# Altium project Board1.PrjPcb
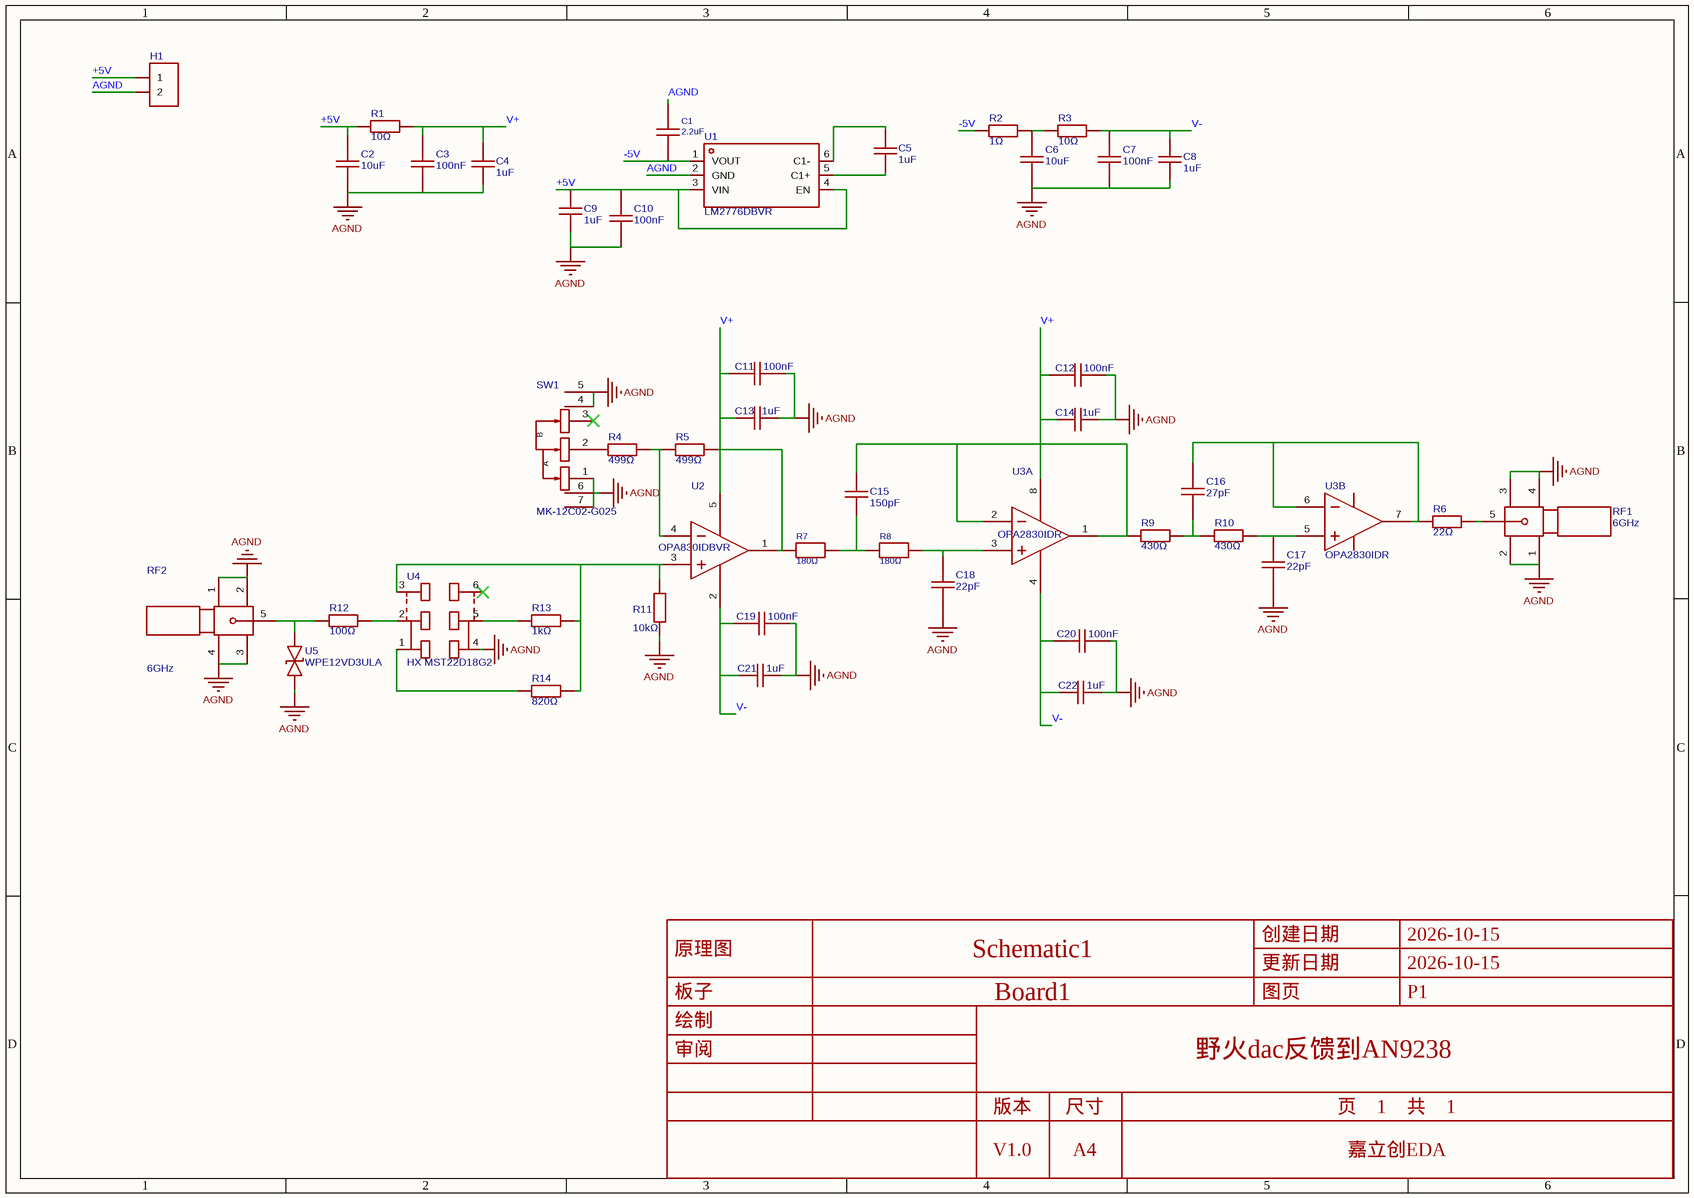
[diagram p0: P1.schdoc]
1 sheet, 45 parts. Net scope: global (net labels, ports and power ports of the same name join across sheets).
Board file: PCB1.pcbdoc

## Sheet P1.schdoc
size 297 x 209 mm; Symbol: Drawing-Symbol_A4; Device: Drawing-Symbol_A4; Company: 嘉立创EDA; Version: V1.0; Page Size: A4; @Project Name: 野火dac反馈到AN9238; @Update Date: 2026-10-15; @Create Date: 2026-10-15; @Board Name: Board1; @Page Name: P1; @Create Time: 21:12:31; @Page Count: 1; @Page No: 1; @Schematic Name: Schematic1; @Update Time: 21:12:31; @Assembly Variant: Basic; Border: 1; Title Block Position: 3; Size: A4; Width: 1170; Height: 825; Region Start: 1; X Region Count: 6; Y Region Count: 4; Blade Width: 10

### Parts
C1  2.2uF  [C0805]
C2  10uF  [C0805]
C3  100nF  [C0603]
C4  1uF  [C0603]
C5  1uF  [C0603]
C6  10uF  [C0805]
C7  100nF  [C0603]
C8  1uF  [C0603]
C9  1uF  [C0603]
C10  100nF  [C0603]
C11  100nF  [C0603]
C12  100nF  [C0603]
C13  1uF  [C0603]
C14  1uF  [C0603]
C15  150pF  [C0603]
C16  27pF  [C0603]
C17  22pF  [C0603]
C18  22pF  [C0603]
C19  100nF  [C0603]
C20  100nF  [C0603]
C21  1uF  [C0603]
C22  1uF  [C0603]
H1  (no value)  [HDR-TH_2P-P2.54-V-F]
R1  10Ω  [R0603]
R2  1Ω  [R0603]
R3  10Ω  [R0603]
R4  499Ω  [R0603]
R5  499Ω  [R0603]
R6  22Ω  [R0603]
R7  180Ω  [R0603]
R8  180Ω  [R0603]
R9  430Ω  [R0603]
R10  430Ω  [R0603]
R11  10kΩ  [R0603]
R12  100Ω  [R0603]
R13  1kΩ  [R0603]
R14  820Ω  [R0603]
RF1  6GHz  [SMA-TH_SMA-KWE902]
RF2  6GHz  [SMA-TH_SMA-KWE902]
SW1  MK-12C02-G025  [SW-SMD_MK-12C02-G025]
U1  LM2776DBVR  [SOT-23-6_L2.9-W1.6-P0.95-LS2.8-BR]
U2  OPA830IDBVR  [SOT-23-5_L2.9-W1.6-P0.95-LS2.8-BR]
U3  OPA2830IDR  [SOIC-8_L5.0-W4.0-P1.27-LS6.0-BL]  (parts A,B of 2)
U4  HX MST22D18G2  [SW-SMD_MST22D18G2]
U5  WPE12VD3ULA  [SOD-323_L1.7-W1.3-LS2.5-BI]

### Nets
AGND: C1.2 C2.1 C3.1 C4.1 C6.1 C7.1 C8.1 C9.1 C10.1 C11.1 C12.1 C13.1 C14.1 C17.1 C18.1 C19.2 C20.2 C21.2 C22.2 H1.2 R11.1 RF1.1 RF1.2 RF1.3 RF1.4 RF2.1 RF2.2 RF2.3 RF2.4 SW1.1 SW1.4 SW1.5 SW1.6 SW1.7 U1.2(GND) U4.4 U5.1
+5V: C2.2 C9.2 C10.2 H1.1 R1.1 U1.3(VIN) U1.4(EN)
-5V: C1.1 R2.1 U1.1(VOUT)
V+: C3.2 C4.2 C11.2 C12.2 C13.2 C14.2 R1.2 U2.5(+VS) U3.8(VS+)
V-: C7.2 C8.2 C19.1 C20.1 C21.1 C22.1 R3.2 U2.2(−VS) U3.4(VS-)
NetC5_1: C5.1 U1.5(C1+)
NetC5_2: C5.2 U1.6(C1-)
NetC6_2: C6.2 R2.2 R3.1
NetC15_1: C15.1 R9.1 U3.1(OUT1) U3.2(IN1-)
NetC15_2: C15.2 R7.2 R8.1
NetC16_1: C16.1 R9.2 R10.1
NetC16_2: C16.2 R6.1 U3.6(IN2-) U3.7(OUT2)
NetC17_2: C17.2 R10.2 U3.5(IN2+)
NetC18_2: C18.2 R8.2 U3.3(IN1+)
NetR4_1: R4.1 SW1.2
NetR4_2: R4.2 R5.1 U2.4(IN-)
NetR5_2: R5.2 R7.1 U2.1(Output)
NetR6_2: R6.2 RF1.5
NetR11_2: R11.2 R13.2 R14.2 U2.3(IN+) U4.3
NetR12_1: R12.1 RF2.5 U5.2
NetR12_2: R12.2 U4.2
NetR13_1: R13.1 U4.5
NetR14_1: R14.1 U4.1

Not connected (* = marked no-connect by the designer): SW1 3*; U4 6*

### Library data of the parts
C1 = CGA0805X7R225M250MT: 容值:2.2uF;精度:±20%;额定电压:25V;温度系数:X7R;; Manufacturer: HRE(芯声); AddInBom: yes; ModelId: 1ba041120af144c991958decab20d2410819f05c4eef4c71ace90d822a990e87; ModelName: C0805_L2.0-W1.3-H1.3; ModelTransform: 78.74,51.181,0,0,0,0,0,0.0005,0; Tolerance: ±20%; Voltage Rating: 25V; Temperature Coefficient: X7R
C2 C6 = 0805X106K250NT: 容值:10uF;精度:±10%;额定电压:25V;温度系数:X5R;; Manufacturer: FH(风华); Symbol: CL21A106KAYNNNE; AddInBom: yes; ModelId: 1ba041120af144c991958decab20d2410819f05c4eef4c71ace90d822a990e87; ModelName: C0805_L2.0-W1.3-H1.3; ModelTransform: 78.74,51.181,0,0,0,0,0,0.0005,0; Tolerance: ±10%; Voltage Rating: 25V; Temperature Coefficient: X5R
C3 C7 C12 C20 = CL10B104KB8NNNC: 容值:100nF;精度:±10%;额定电压:50V;温度系数:X7R;; Manufacturer: SAMSUNG(三星); AddInBom: yes; ModelId: ac125912035d415993ca9572d50418b10819f05c4eef4c71ace90d822a990e87; ModelName: C0603_L1.6-W0.8-H0.8; ModelTransform: 62.992,31.496,0,0,0,0,0,0,0; Tolerance: ±10%; Voltage Rating: 50V; Temperature Coefficient: X7R
C4 C8 C14 C22 = CL10A105KA8NNNC: 容值:1uF;精度:±10%;额定电压:25V;温度系数:X5R;; Manufacturer: SAMSUNG(三星); AddInBom: yes; ModelId: ac125912035d415993ca9572d50418b10819f05c4eef4c71ace90d822a990e87; ModelName: C0603_L1.6-W0.8-H0.8; ModelTransform: 62.992,31.496,0,0,0,0,0,0,0; Tolerance: ±10%; Voltage Rating: 25V; Temperature Coefficient: X5R
C5 C9 C13 C21 = CL10A105KA8NNNC: 容值:1uF;精度:±10%;额定电压:25V;温度系数:X5R;; Manufacturer: SAMSUNG(三星); 3D Model: ac125912035d415993ca9572d50418b10819f05c4eef4c71ace90d822a990e87; 3D Model Transform: 62.992,31.496,0,0,0,0,0,0,0; Tolerance: ±10%; Voltage Rating: 25V; Temperature Coefficient: X5R; AddInBom: yes; ModelName: C0603_L1.6-W0.8-H0.8
C10 C11 C19 = CL10B104KB8NNNC: 容值:100nF;精度:±10%;额定电压:50V;温度系数:X7R;; Manufacturer: SAMSUNG(三星); 3D Model: ac125912035d415993ca9572d50418b10819f05c4eef4c71ace90d822a990e87; 3D Model Transform: 62.992,31.496,0,0,0,0,0,0,0; Tolerance: ±10%; Voltage Rating: 50V; Temperature Coefficient: X7R; AddInBom: yes; ModelName: C0603_L1.6-W0.8-H0.8
C15 = 0603CG151J500NT: 容值:150pF;精度:±5%;额定电压:50V;温度系数:C0G;; Manufacturer: FH(风华); AddInBom: yes; ModelId: ac125912035d415993ca9572d50418b10819f05c4eef4c71ace90d822a990e87; ModelName: C0603_L1.6-W0.8-H0.8; ModelTransform: 62.992,31.496,0,0,0,0,0,0,0; Tolerance: ±5%; Voltage Rating: 50V; Temperature Coefficient: C0G
C16 = 0603CG270J500NT: 容值:27pF;精度:±5%;额定电压:50V;温度系数:C0G;; Manufacturer: FH(风华); AddInBom: yes; ModelId: ac125912035d415993ca9572d50418b10819f05c4eef4c71ace90d822a990e87; ModelName: C0603_L1.6-W0.8-H0.8; ModelTransform: 62.992,31.496,0,0,0,0,0,0,0; Tolerance: ±5%; Voltage Rating: 50V; Temperature Coefficient: C0G
C17 C18 = 0603CG220J500NT: 容值:22pF;精度:±5%;额定电压:50V;温度系数:C0G;; Manufacturer: FH(风华); AddInBom: yes; ModelId: ac125912035d415993ca9572d50418b10819f05c4eef4c71ace90d822a990e87; ModelName: C0603_L1.6-W0.8-H0.8; ModelTransform: 62.992,31.496,0,0,0,0,0,0,0; Tolerance: ±5%; Voltage Rating: 50V; Temperature Coefficient: C0G
H1 = HDR-F_2.54_1x2P: Symbol: Header-Female-2.54_1x2; ConvertToPcb: yes; ModelId: a9450ef445564560a104363b9aacde4e0819f05c4eef4c71ace90d822a990e87; ModelName: HDR-TH_2P-P2.54-F-LI-1X2P; ModelTransform: 215.7476,98.425,0,0,0,0,0,0,-129.921
R1 R3 = 0603WAF100JT5E: 电阻类型:厚膜电阻;阻值:10Ω;精度:±1%;功率:100mW;工作电压:75V;温度系数:±400ppm/℃;; Manufacturer: UNI-ROYAL(厚声); AddInBom: yes; ModelId: fc143cca1e79419f9cd78b61e9279f080819f05c4eef4c71ace90d822a990e87; ModelTransform: 31.8897,63.7794,0,90,0,0,0,0,0; Tolerance: ±1%; Power(Watts): 100mW; Voltage-Supply(Max): 75V
R2 = AC0603FR-071RL: 电阻类型:厚膜电阻;阻值:1Ω;精度:±1%;功率:100mW;工作电压:75V;温度系数:±200ppm/℃;; Manufacturer: YAGEO(国巨); Symbol: 0603WAF100KT5E; AddInBom: yes; ModelId: fc143cca1e79419f9cd78b61e9279f080819f05c4eef4c71ace90d822a990e87; ModelTransform: 31.8897,63.7794,0,90,0,0,0,0,0; Tolerance: ±1%; Power(Watts): 100mW; Voltage-Supply(Max): 75V
R4 R5 = RC0603FR-07499RL: 电阻类型:厚膜电阻;阻值:499Ω;精度:±1%;功率:100mW;工作电压:75V;温度系数:±100ppm/℃;; Manufacturer: YAGEO(国巨); AddInBom: yes; ModelId: fc143cca1e79419f9cd78b61e9279f080819f05c4eef4c71ace90d822a990e87; ModelTransform: 31.8897,63.7794,0,90,0,0,0,0,0; Tolerance: ±1%; Power(Watts): 100mW; Voltage-Supply(Max): 75V
R6 = 0603WAF220JT5E: 电阻类型:厚膜电阻;阻值:22Ω;精度:±1%;功率:100mW;最大工作电压:75V;温度系数:±100ppm/℃;; Manufacturer: UNI-ROYAL(厚声); AddInBom: yes; ModelId: fc143cca1e79419f9cd78b61e9279f080819f05c4eef4c71ace90d822a990e87; ModelTransform: 31.8897,63.7794,0,90,0,0,0,0,0; Tolerance: ±1%; Power(Watts): 100mW; Overload Voltage (Max): 75V
R7 R8 = 1RC0603F1800: 电阻类型:厚膜电阻;阻值:180Ω;精度:±1%;功率:100mW;工作电压:75V;温度系数:±100ppm/℃;; Manufacturer: SAE(世盟/世爱); AddInBom: yes; ModelId: fc143cca1e79419f9cd78b61e9279f080819f05c4eef4c71ace90d822a990e87; ModelTransform: 31.8897,63.7794,0,90,0,0,0,0,0; Tolerance: ±1%; Power(Watts): 100mW; Voltage-Supply(Max): 75V
R9 R10 = 0603WAF4300T5E: 电阻类型:厚膜电阻;阻值:430Ω;精度:±1%;功率:100mW;工作电压:75V;温度系数:±100ppm/℃;; Manufacturer: UNI-ROYAL(厚声); AddInBom: yes; ModelId: fc143cca1e79419f9cd78b61e9279f080819f05c4eef4c71ace90d822a990e87; ModelTransform: 31.8897,63.7794,0,90,0,0,0,0,0; Tolerance: ±1%; Power(Watts): 100mW; Voltage-Supply(Max): 75V
R11 = RC0603FR-0710KL: 电阻类型:厚膜电阻;阻值:10kΩ;精度:±1%;功率:100mW;工作电压:75V;温度系数:±100ppm/℃;; Manufacturer: YAGEO(国巨); Symbol: 0603WAF1002T5E; AddInBom: yes; ModelId: fc143cca1e79419f9cd78b61e9279f080819f05c4eef4c71ace90d822a990e87; ModelTransform: 31.8897,63.7794,0,90,0,0,0,0,0; Tolerance: ±1%; Power(Watts): 100mW; Voltage-Supply(Max): 75V
R12 = 0603WAF1000T5E: 电阻类型:厚膜电阻;阻值:100Ω;精度:±1%;功率:100mW;最大工作电压:75V;温度系数:±200ppm/℃;; Manufacturer: UNI-ROYAL(厚声); AddInBom: yes; ModelId: fc143cca1e79419f9cd78b61e9279f080819f05c4eef4c71ace90d822a990e87; ModelTransform: 31.8897,63.7794,0,90,0,0,0,0,0; Tolerance: ±1%; Power(Watts): 100mW; Overload Voltage (Max): 75V
R13 = 0603WAF1001T5E: 电阻类型:厚膜电阻;阻值:1kΩ;精度:±1%;功率:100mW;工作电压:75V;温度系数:±100ppm/℃;; Manufacturer: UNI-ROYAL(厚声); AddInBom: yes; ModelId: fc143cca1e79419f9cd78b61e9279f080819f05c4eef4c71ace90d822a990e87; ModelTransform: 31.8897,63.7794,0,90,0,0,0,0,0; Tolerance: ±1%; Power(Watts): 100mW; Voltage-Supply(Max): 75V
R14 = 0603WAF8200T5E: 电阻类型:厚膜电阻;阻值:820Ω;精度:±1%;功率:100mW;工作电压:75V;温度系数:±100ppm/℃;; Manufacturer: UNI-ROYAL(厚声); AddInBom: yes; ModelId: fc143cca1e79419f9cd78b61e9279f080819f05c4eef4c71ace90d822a990e87; ModelTransform: 31.8897,63.7794,0,90,0,0,0,0,0; Tolerance: ±1%; Power(Watts): 100mW; Voltage-Supply(Max): 75V
RF1 RF2 = SMA-KWE902: 连接器类型:板端;接口类型:内孔;端口数量:1;接口直径:5.35mm;接口长度/高度:-;频率:6GHz;射频系列:SMA;阻抗:50Ω;样式:弯头;工作温度:-55℃~+125℃;; Manufacturer: DreamLNK(骏晔科技); AddInBom: yes; ModelId: eb1fe0e9f7df46ddbf3a02de7734a0a30819f05c4eef4c71ace90d822a990e87; ModelTransform: 275.59,594.487,0,180,0,0,0,159.449,-145.669; Connector Type: 板端; Interface: 内孔; Number of Ports: 1; Interface Diameter: 5.35mm; RF Series: SMA; Impedance: 50Ω; Style: 弯头
SW1 = MK-12C02-G025: 电路结构:单刀双掷;安装方式:卧贴;开关颜色:黑色;额定电流:-;额定电压:-;工作寿命:-;; Manufacturer: G-Switch(品赞); AddInBom: yes; ModelId: 2dfca800947d41659e167f5790de33390819f05c4eef4c71ace90d822a990e87; ModelTransform: 303.149,204.724,0,0,0,0,-0.004,-27.102,0; Circuit: 单刀双掷; Actuator Style: 矩形柱状; Switch Height: 5.2mm; Actuator Color: 黑色
U1 = LM2776DBVR: LM2776 开关电容器反相器; Manufacturer: TI(德州仪器); AddInBom: yes; ModelId: 18da8f6c14a34920b3e136b5c401a1190819f05c4eef4c71ace90d822a990e87; ModelName: SOT-23-6_L2.9-W1.6-H1.5-LS2.8-P0.95; ModelTransform: 110.73671,114.173,0,180,0,0,0.001,-0.003,0; Function: 反相; Operating Voltage: 2.7V~5.5V; Output Voltage: -5.5V~-2.7V; Output Current: 200mA; Quiescent Current: 200uA; Output Resistance: 2.5Ω; Energy Efficiency: 90%; Switching Frequency: 2MHz; PFM Mode: 支持
U2 = OPA830IDBVR: 放大器数:1;轨到轨:-;增益带宽积(GBW):110MHz;输入失调电压(Vos):6.5mV;压摆率(SR):550V/us;输入偏置电流(Ib):13uA;; Manufacturer: TI(德州仪器); AddInBom: yes; ModelId: 7ba65df16e7b4570af156e925f9c37fe0819f05c4eef4c71ace90d822a990e87; ModelTransform: 114.173,114.173,0,90,0,0,0,0,0; Number of Channels: 1; Gain Bandwidth Product: 110MHz; Vos - Input Offset Voltage: 6.5mV; Input Offset Voltage Drift(Vos TC): 20uV/℃; Ib - Input Bias Current: 13uA; Input Offset Current(Ios): 1.2uA; Input Voltage Noise Density: 9.2nV/√Hz@1MHz; Common Mode Rejection Ratio(CMRR): 72dB; Quiescent Current: 5.9mA; Output Current: 80mA; Single supply: 2.8V~11V; Dual Supply: -5.5V~-1.4V；1.4V~5.5V
U3 = OPA2830IDR: 放大器数:2;轨到轨:-;增益带宽积(GBW):100MHz;输入失调电压(Vos):1.5mV;压摆率(SR):560V/us;输入偏置电流(Ib):5uA;; Manufacturer: TI(德州仪器); Relevance: []; AddInBom: yes; ModelId: 7abc64c95a1a4a04a4ef38f9097c870b0819f05c4eef4c71ace90d822a990e87; ModelTransform: 192.913,236.22,0,0,0,0,0,0,0; Number of Channels: 2; Gain Bandwidth Product: 100MHz; Vos - Input Offset Voltage: 1.5mV; Input Offset Voltage Drift(Vos TC): 22uV/℃; Ib - Input Bias Current: 5uA; Input Offset Current(Ios): 200nA; Input Voltage Noise Density: 9.2nV/√Hz@1MHz; Common Mode Rejection Ratio(CMRR): 80dB; Quiescent Current: 7.8mA; Output Current: 75mA; Single supply: 3.2V~11V; Dual Supply: -5.5V~5.5V
U4 = HX MST22D18G2: 电路结构:双刀双掷;安装方式:立贴;开关颜色:黑色;额定电流:100mA;额定电压:12V;工作寿命:1万次;; Manufacturer: hanxia(韩下); AddInBom: yes; ModelId: 13bef5fa0df644de8c9e1e9205077fe70819f05c4eef4c71ace90d822a990e87; ModelTransform: 354.33,269.685,0,0,0,0,0,0,0; Circuit: 双刀双掷; Actuator Style: 矩形柱状; Switch Height: 5.5mm; Actuator Color: 黑色; Current Rating: 100mA; Voltage Rating: 12V; Life: 1万次
U5 = WPE12VD3ULA: 极性:双向;反向截止电压(Vrwm):12V;钳位电压:29V;峰值脉冲电流(Ipp):12A@8/20us;峰值脉冲功率(Ppp):350W@8/20us;击穿电压(VBR):13.3V;; Manufacturer: WPMtek(维攀); AddInBom: yes; ModelId: 3c4d3117213c44d8be2b8463c3660d200819f05c4eef4c71ace90d822a990e87; ModelTransform: 98.425,51.181,0,0,0,0,-0.001,0.006,0; Polarity: 双向; Reverse Stand-Off Voltage (Vrwm): 12V; Clamping Voltage: 29V; Voltage - Breakdown: 13.3V; Reverse Leakage Current (Ir): 200nA; Number of Channels: 单路; level of protection: IEC 61000-4-5；IEC 61000-4-2; Junction Capacitance: 1pF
